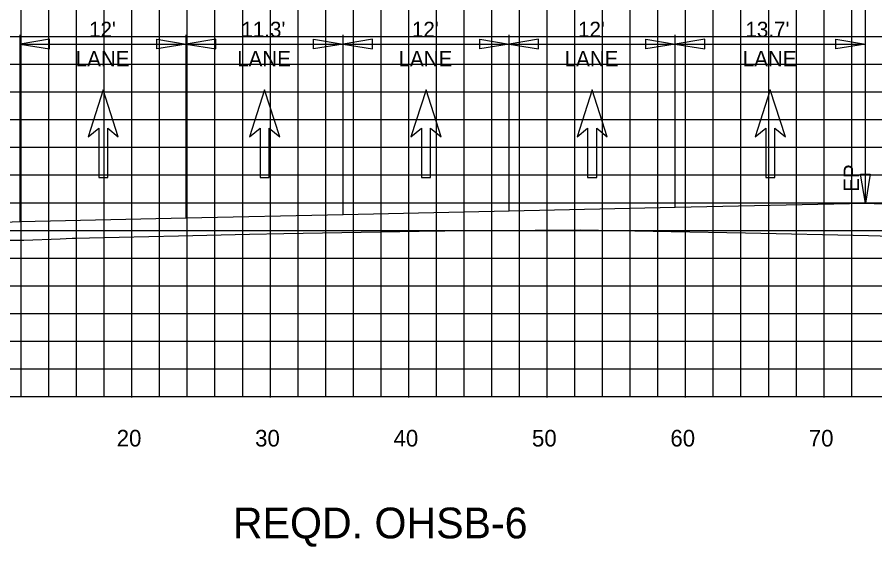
# Model space of a CAD drawing. Extents: x 2193008 to 2198143, y 1236112 to 1237864.
# Drawn here: x 2195596.4 to 2195658.4, y 1237152.3 to 1237190.5 of the extents above; entities that cross this region are included whole.
import ezdxf

# ---------------------------------------------------------------- set-up
doc = ezdxf.new("R2010")
doc.units = 0
for name, color, linetype in [('3', 7, 'Continuous'), ('60', 7, 'Continuous'), ('GSDIMS', 7, 'Continuous'), ('Level 28', 7, 'Continuous'), ('Level 55', 7, 'Continuous'), ('LIMT-CSLINE', 7, 'Continuous'), ('M-ROADS', 7, 'Continuous')]:
    doc.layers.add(name, color=color, linetype=linetype)

msp = doc.modelspace()

# ---------------------------------------------------------------- linework, layer by layer
at = {"layer": '3'}
for p, q in [((2195657.692, 1237177.083), (2195657.692, 1237195.083)), ((2195596.632, 1237175.74), (2195596.632, 1237189.222)), ((2195608.634, 1237176.004), (2195608.634, 1237189.222)), ((2195619.956, 1237176.253), (2195619.956, 1237189.222)), ((2195631.956, 1237176.517), (2195631.956, 1237189.222)), ((2195643.956, 1237176.781), (2195643.956, 1237189.222))]:
    msp.add_line(p, q, dxfattribs=at)
at = {"layer": '60'}
for p, q in [((2195584.707, 1237163.106), (2195714.707, 1237163.106)), ((2195604.707, 1237163.046), (2195604.707, 1237163.106)), ((2195614.707, 1237163.046), (2195614.707, 1237163.106)), ((2195624.707, 1237163.046), (2195624.707, 1237163.106)), ((2195634.707, 1237163.046), (2195634.707, 1237163.106)), ((2195644.707, 1237163.046), (2195644.707, 1237163.106)), ((2195654.707, 1237163.046), (2195654.707, 1237163.106))]:
    msp.add_line(p, q, dxfattribs=at)
msp.add_lwpolyline([(2195587.2, 1237175.362), (2195596.632, 1237175.74), (2195608.634, 1237176.004), (2195619.956, 1237176.253), (2195631.956, 1237176.517), (2195643.956, 1237176.781), (2195657.692, 1237177.083), (2195669.692, 1237176.603), (2195671.692, 1237176.523), (2195675.192, 1237176.383), (2195690.656, 1237171.228)], dxfattribs=at)
at = {"layer": 'GSDIMS'}
for p, q in [((2195596.632, 1237188.559), (2195608.634, 1237188.559)), ((2195608.634, 1237188.559), (2195619.956, 1237188.559)), ((2195619.956, 1237188.559), (2195631.956, 1237188.559)), ((2195631.956, 1237188.559), (2195643.956, 1237188.559)), ((2195643.956, 1237188.559), (2195657.692, 1237188.559))]:
    msp.add_line(p, q, dxfattribs=at)
for points in [[(2195596.632, 1237188.559), (2195598.761, 1237188.212), (2195598.761, 1237188.907)], [(2195608.634, 1237188.559), (2195606.505, 1237188.212), (2195606.505, 1237188.907)], [(2195608.634, 1237188.559), (2195610.762, 1237188.212), (2195610.762, 1237188.907)], [(2195619.956, 1237188.559), (2195617.828, 1237188.212), (2195617.828, 1237188.907)], [(2195619.956, 1237188.559), (2195622.084, 1237188.212), (2195622.084, 1237188.907)], [(2195631.956, 1237188.559), (2195629.828, 1237188.212), (2195629.828, 1237188.907)], [(2195631.956, 1237188.559), (2195634.084, 1237188.212), (2195634.084, 1237188.907)], [(2195643.956, 1237188.559), (2195641.828, 1237188.212), (2195641.828, 1237188.907)], [(2195643.956, 1237188.559), (2195646.084, 1237188.212), (2195646.084, 1237188.907)], [(2195657.692, 1237188.559), (2195655.563, 1237188.212), (2195655.563, 1237188.907)], [(2195657.692, 1237177.083), (2195657.337, 1237179.166), (2195658.046, 1237179.166)]]:
    msp.add_lwpolyline(points, close=True, dxfattribs=at)
at = {"layer": 'Level 28'}
for p, q in [((2195602.633, 1237185.25), (2195601.544, 1237181.852)), ((2195603.722, 1237181.852), (2195602.633, 1237185.25)), ((2195614.295, 1237185.25), (2195613.206, 1237181.852)), ((2195615.384, 1237181.852), (2195614.295, 1237185.25)), ((2195625.956, 1237185.25), (2195624.867, 1237181.852)), ((2195627.045, 1237181.852), (2195625.956, 1237185.25)), ((2195637.956, 1237185.25), (2195636.867, 1237181.852)), ((2195639.045, 1237181.852), (2195637.956, 1237185.25)), ((2195650.824, 1237185.25), (2195649.735, 1237181.852)), ((2195651.913, 1237181.852), (2195650.824, 1237185.25)), ((2195601.544, 1237181.852), (2195602.306, 1237182.491)), ((2195602.306, 1237182.491), (2195602.306, 1237178.92)), ((2195602.96, 1237178.92), (2195602.96, 1237182.491)), ((2195602.96, 1237182.491), (2195603.722, 1237181.852)), ((2195613.206, 1237181.852), (2195613.968, 1237182.491)), ((2195613.968, 1237182.491), (2195613.968, 1237178.92)), ((2195614.622, 1237178.92), (2195614.622, 1237182.491)), ((2195614.622, 1237182.491), (2195615.384, 1237181.852)), ((2195624.867, 1237181.852), (2195625.629, 1237182.491)), ((2195625.629, 1237182.491), (2195625.629, 1237178.92)), ((2195626.283, 1237178.92), (2195626.283, 1237182.491)), ((2195626.283, 1237182.491), (2195627.045, 1237181.852)), ((2195636.867, 1237181.852), (2195637.629, 1237182.491)), ((2195637.629, 1237182.491), (2195637.629, 1237178.92)), ((2195638.283, 1237178.92), (2195638.283, 1237182.491)), ((2195638.283, 1237182.491), (2195639.045, 1237181.852)), ((2195649.735, 1237181.852), (2195650.497, 1237182.491)), ((2195650.497, 1237182.491), (2195650.497, 1237178.92)), ((2195651.151, 1237178.92), (2195651.151, 1237182.491)), ((2195651.151, 1237182.491), (2195651.913, 1237181.852)), ((2195602.306, 1237178.92), (2195602.96, 1237178.92)), ((2195613.968, 1237178.92), (2195614.622, 1237178.92)), ((2195625.629, 1237178.92), (2195626.283, 1237178.92)), ((2195637.629, 1237178.92), (2195638.283, 1237178.92)), ((2195650.497, 1237178.92), (2195651.151, 1237178.92))]:
    msp.add_line(p, q, dxfattribs=at)
at = {"layer": 'M-ROADS'}
for p, q in [((2195596.707, 1237163.106), (2195596.707, 1237223.106)), ((2195598.707, 1237163.106), (2195598.707, 1237223.106)), ((2195600.707, 1237163.106), (2195600.707, 1237223.106)), ((2195602.707, 1237163.106), (2195602.707, 1237223.106)), ((2195604.707, 1237163.106), (2195604.707, 1237223.106)), ((2195606.707, 1237163.106), (2195606.707, 1237223.106)), ((2195608.707, 1237163.106), (2195608.707, 1237223.106)), ((2195610.707, 1237163.106), (2195610.707, 1237223.106)), ((2195612.707, 1237163.106), (2195612.707, 1237223.106)), ((2195614.707, 1237163.106), (2195614.707, 1237223.106)), ((2195616.707, 1237163.106), (2195616.707, 1237223.106)), ((2195618.707, 1237163.106), (2195618.707, 1237223.106)), ((2195620.707, 1237163.106), (2195620.707, 1237223.106)), ((2195622.707, 1237163.106), (2195622.707, 1237223.106)), ((2195624.707, 1237163.106), (2195624.707, 1237223.106)), ((2195626.707, 1237163.106), (2195626.707, 1237223.106)), ((2195628.707, 1237163.106), (2195628.707, 1237223.106)), ((2195630.707, 1237163.106), (2195630.707, 1237223.106)), ((2195632.707, 1237163.106), (2195632.707, 1237223.106)), ((2195634.707, 1237163.106), (2195634.707, 1237223.106)), ((2195636.707, 1237163.106), (2195636.707, 1237223.106)), ((2195638.707, 1237163.106), (2195638.707, 1237223.106)), ((2195640.707, 1237163.106), (2195640.707, 1237223.106)), ((2195642.707, 1237163.106), (2195642.707, 1237223.106)), ((2195644.707, 1237163.106), (2195644.707, 1237223.106)), ((2195646.707, 1237163.106), (2195646.707, 1237223.106)), ((2195648.707, 1237163.106), (2195648.707, 1237223.106)), ((2195650.707, 1237163.106), (2195650.707, 1237223.106)), ((2195652.707, 1237163.106), (2195652.707, 1237223.106)), ((2195654.707, 1237163.106), (2195654.707, 1237223.106)), ((2195656.707, 1237163.106), (2195656.707, 1237223.106)), ((2195584.707, 1237189.106), (2195714.707, 1237189.106)), ((2195584.707, 1237187.106), (2195714.707, 1237187.106)), ((2195584.707, 1237185.106), (2195714.707, 1237185.106)), ((2195584.707, 1237183.106), (2195714.707, 1237183.106)), ((2195584.707, 1237181.106), (2195714.707, 1237181.106)), ((2195584.707, 1237179.106), (2195714.707, 1237179.106)), ((2195584.707, 1237177.106), (2195714.707, 1237177.106)), ((2195584.707, 1237175.106), (2195714.707, 1237175.106)), ((2195584.707, 1237173.106), (2195714.707, 1237173.106)), ((2195584.707, 1237171.106), (2195714.707, 1237171.106)), ((2195584.707, 1237169.106), (2195714.707, 1237169.106)), ((2195584.707, 1237167.106), (2195714.707, 1237167.106)), ((2195584.707, 1237165.106), (2195714.707, 1237165.106)), ((2195584.707, 1237163.106), (2195714.707, 1237163.106))]:
    msp.add_line(p, q, dxfattribs=at)
msp.add_lwpolyline([(2195584.707, 1237174.638), (2195585.628, 1237174.618), (2195585.966, 1237174.599), (2195586.873, 1237174.555), (2195587.872, 1237174.51), (2195590.054, 1237174.412), (2195595.308, 1237174.402), (2195596.894, 1237174.4), (2195599.516, 1237174.504), (2195600.392, 1237174.538), (2195600.737, 1237174.552), (2195601.636, 1237174.58), (2195608.061, 1237174.725), (2195613.203, 1237174.839), (2195615.685, 1237174.891), (2195625.468, 1237175.06), (2195627.311, 1237175.07), (2195637.121, 1237175.142), (2195643.667, 1237175.037), (2195649.033, 1237174.936), (2195657.92, 1237174.726), (2195662.188, 1237174.616)], dxfattribs=at)

# ---------------------------------------------------------------- texts
at = {"layer": 'Level 55'}
for s, height, p in [("12'", 1.1105, (2195601.612, 1237189.059)), ("11.3'", 1.1105, (2195612.616, 1237189.059)), ("12'", 1.1105, (2195624.935, 1237189.059)), ("12'", 1.1105, (2195636.935, 1237189.059)), ("13.7'", 1.1105, (2195649.031, 1237189.059)), ('LANE', 1.1105, (2195600.647, 1237186.949)), ('LANE', 1.1105, (2195612.309, 1237186.949)), ('LANE', 1.1105, (2195623.97, 1237186.949)), ('LANE', 1.1105, (2195635.97, 1237186.949)), ('LANE', 1.1105, (2195648.838, 1237186.949)), ('REQD. OHSB-6', 2.22092, (2195611.999, 1237152.873))]:
    msp.add_text(s, height=height, dxfattribs=at).set_placement(p)
msp.add_text('EP', height=1.1105, rotation=90, dxfattribs=at).set_placement((2195657.239, 1237177.892))
at = {"layer": 'LIMT-CSLINE'}
for s, p in [('20', (2195603.606, 1237159.506)), ('30', (2195613.606, 1237159.506)), ('40', (2195623.606, 1237159.506)), ('50', (2195633.606, 1237159.506)), ('60', (2195643.606, 1237159.506)), ('70', (2195653.606, 1237159.506))]:
    msp.add_text(s, height=1.2, dxfattribs=at).set_placement(p)

doc.saveas('drawing.dxf')
